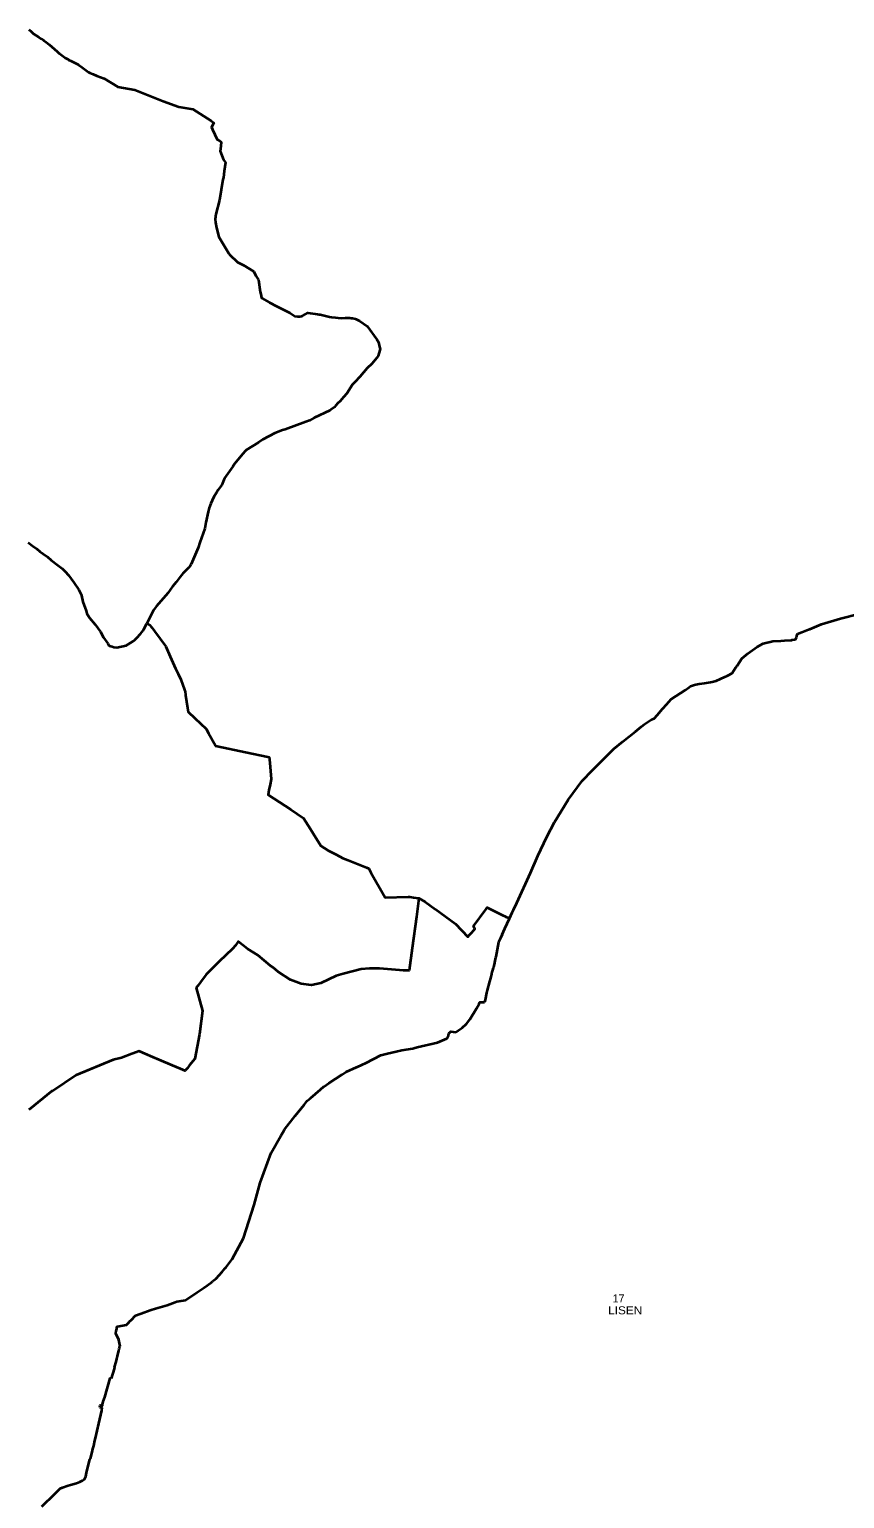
# Model space of a CAD drawing. Extents: x -610940 to -588976, y -1170376 to -1149800.
# Drawn here: x -594068 to -591522, y -1160628 to -1156037 of the extents above; entities that cross this region are included whole.
import ezdxf

# ---------------------------------------------------------------- set-up
doc = ezdxf.new("R2010")
doc.units = 0
doc.header["$LTSCALE"] = 10
doc.layers.add('54', color=7, linetype='Continuous', lineweight=35)
doc.layers.add('55', color=7, linetype='Continuous')
doc.layers.add('56', color=7, linetype='Continuous')

msp = doc.modelspace()

# ---------------------------------------------------------------- linework, layer by layer
at = {"layer": '54'}
for p, q in [((-592620.5, -1158973.98), (-592623.43, -1158983.47)), ((-592619.05, -1158968.17), (-592620.5, -1158973.98)), ((-592659.46, -1159076.98), (-592658.44, -1159076.99)), ((-592655.5, -1159077.04), (-592647.48, -1159077.18)), ((-592744.47, -1159169.7), (-592736.44, -1159170.78)), ((-593237.63, -1159432.35), (-593209.8, -1159397.39)), ((-593701.88, -1160043.06), (-593688.14, -1160038.12)), ((-593841.53, -1160352.31), (-593840.77, -1160344.11)), ((-594000.97, -1160625), (-593995.65, -1160620))]:
    msp.add_line(p, q, dxfattribs=at)
for points in [[(-594069.79, -1156037.15), (-594062.47, -1156043.95), (-594055.33, -1156050.58), (-594054.77, -1156050.95), (-594046.76, -1156056.24), (-594039.02, -1156061.36), (-594031.05, -1156066.63), (-594023.9, -1156071.35), (-594023.26, -1156071.81), (-594015.19, -1156077.58), (-594006.33, -1156083.91), (-594005.96, -1156084.24), (-593998.04, -1156091.35), (-593990, -1156098.56), (-593981.65, -1156106.05), (-593976.34, -1156111.24), (-593973.67, -1156112.71), (-593965.38, -1156119), (-593961.28, -1156122.1), (-593955.87, -1156125.6), (-593946.37, -1156131.73), (-593946.13, -1156131.84), (-593936.72, -1156136.45), (-593925.95, -1156141.72), (-593916.16, -1156146.52), (-593915.09, -1156147.46), (-593914.77, -1156147.68), (-593904.17, -1156155.24), (-593891.43, -1156164.31), (-593883.88, -1156170.56), (-593879.19, -1156172.57), (-593869.12, -1156177.32), (-593857.62, -1156182.75)], [(-593857.62, -1156182.75), (-593834.8, -1156190.12), (-593791.84, -1156217), (-593738.88, -1156226.42), (-593733.86, -1156228.63), (-593702.14, -1156241.11), (-593649.76, -1156261.34), (-593601.64, -1156279.3), (-593557.9, -1156286.82), (-593499.91, -1156322.68), (-593491.52, -1156329.58), (-593499.53, -1156342.24), (-593495.97, -1156350.49), (-593481.7, -1156380.78), (-593476.08, -1156383.18), (-593468.86, -1156389.28), (-593470.91, -1156410.93), (-593472.55, -1156417.18), (-593462.02, -1156445.06), (-593455.69, -1156452.71), (-593459.58, -1156480.35), (-593462.01, -1156500.12), (-593463.43, -1156506.51), (-593474.75, -1156571.22), (-593485.63, -1156614.98), (-593487.32, -1156630.19), (-593486.55, -1156640.25), (-593483.25, -1156657.26), (-593475.86, -1156685.73), (-593445.64, -1156737.9), (-593443.48, -1156740.73), (-593417.94, -1156765.02), (-593399.28, -1156773.41), (-593366.69, -1156793.65), (-593360.55, -1156806.97), (-593352.81, -1156820.08), (-593346.99, -1156856.74), (-593345.5, -1156864.12), (-593343.51, -1156875.89), (-593342.45, -1156876.95)], [(-593342.45, -1156876.95), (-593318.56, -1156890.33), (-593296.11, -1156902.49), (-593255.02, -1156922.92), (-593238.86, -1156932.97), (-593230.3, -1156934.39), (-593226.2, -1156934.61), (-593222.89, -1156934.51), (-593218.56, -1156933.69), (-593214.88, -1156932.45), (-593205.61, -1156927.12), (-593198.08, -1156923), (-593167.89, -1156927.3), (-593163.45, -1156927.68), (-593159.39, -1156928.25), (-593130.71, -1156935.56), (-593124.59, -1156936.71), (-593112.37, -1156937.72), (-593104.12, -1156938.75), (-593092.74, -1156939.19), (-593081.51, -1156938.49), (-593070.1, -1156938.27), (-593066.78, -1156938.36), (-593063.13, -1156939.04), (-593059.37, -1156940), (-593049.81, -1156942.01), (-593048.18, -1156942.57), (-593047.13, -1156942.92), (-593036.74, -1156948.05), (-593013.44, -1156964.31), (-592983.04, -1157006.13), (-592977.4, -1157014.4), (-592974.55, -1157029.02), (-592972.78, -1157035.67), (-592973.65, -1157039.42), (-592978.42, -1157057.33), (-592983.09, -1157063), (-592998.57, -1157082.68), (-593013.1, -1157095.82), (-593035.93, -1157122.97)], [(-593035.93, -1157122.97), (-593052, -1157139.17), (-593058.82, -1157146.28), (-593076.67, -1157174.69), (-593086.92, -1157186.59), (-593097.44, -1157199.16), (-593104.17, -1157205.57), (-593112.11, -1157213.61), (-593115.5, -1157217.85), (-593125.7, -1157225.03), (-593129.55, -1157227.92), (-593178.36, -1157251.26), (-593193.66, -1157258.82), (-593204.39, -1157263.8), (-593268.82, -1157287.15), (-593277.57, -1157289.02), (-593301.05, -1157298.73), (-593338.79, -1157318.69), (-593352.55, -1157327.64), (-593390.06, -1157350.68), (-593394.27, -1157355.03), (-593401.38, -1157363.13), (-593427.12, -1157394.33), (-593433.05, -1157402.77), (-593458.23, -1157439.86), (-593463.08, -1157450.12), (-593467.16, -1157459.95), (-593478.58, -1157476.08), (-593483.1, -1157483.24), (-593491.64, -1157498.04), (-593497.4, -1157508.92), (-593501.35, -1157518.21), (-593506.52, -1157532.12), (-593510.06, -1157544.44), (-593516.89, -1157578.14), (-593520.5, -1157596.82), (-593535.54, -1157640.12), (-593540.82, -1157656.62), (-593550.38, -1157679.12), (-593562.92, -1157707.85)], [(-594072.16, -1157640.36), (-594058.55, -1157650.67), (-594045.24, -1157660.51), (-594035.66, -1157668.28), (-594024.77, -1157675.54), (-594011.9, -1157685.55), (-594000.02, -1157695.45), (-593978.19, -1157712.07), (-593966.14, -1157721.54), (-593956.07, -1157730.91), (-593945.72, -1157742.84), (-593929.39, -1157765.22), (-593929.13, -1157765.62), (-593913.95, -1157788.72), (-593907.32, -1157801.34), (-593905.73, -1157805.8), (-593900.74, -1157825.38), (-593891.09, -1157853.98)], [(-593562.92, -1157707.85), (-593566.26, -1157713.46), (-593570.58, -1157718.98), (-593577.13, -1157725.77), (-593588.64, -1157737.11), (-593597.16, -1157747.75), (-593609.73, -1157763.95), (-593620.6, -1157777.65), (-593635.75, -1157798.36), (-593671.14, -1157839.67), (-593680.79, -1157852.12), (-593701.01, -1157893.15)], [(-593891.09, -1157853.98), (-593888.32, -1157862.18), (-593880.11, -1157875.63), (-593862.71, -1157896.26), (-593845.59, -1157919.5), (-593836.19, -1157937.04), (-593823.05, -1157956.32), (-593819.62, -1157962.1), (-593818.37, -1157962.89), (-593809.36, -1157965.88), (-593804.56, -1157967.18), (-593795.33, -1157968.43), (-593765.63, -1157961.83), (-593760.93, -1157959.27), (-593744.41, -1157949.12), (-593740.22, -1157946.06), (-593737.6, -1157943.27), (-593732.15, -1157937.94), (-593720.85, -1157925.34), (-593712.5, -1157915.49), (-593710.45, -1157911.1), (-593701.01, -1157893.15), (-593692.37, -1157898.58), (-593688.12, -1157903.54), (-593685.85, -1157906.48), (-593677.56, -1157917.18), (-593641.93, -1157965.55), (-593628.14, -1157997.11), (-593620.22, -1158015.22), (-593611.33, -1158033.93), (-593603.82, -1158050.67), (-593595.12, -1158068.75), (-593583.43, -1158100.91), (-593582.41, -1158103.73), (-593581.75, -1158104.67), (-593580.19, -1158117.8), (-593574.21, -1158156.71), (-593572.44, -1158169.19), (-593551.34, -1158189.22), (-593516.26, -1158222.24)], [(-591890.72, -1158057.76), (-591879.98, -1158052.5), (-591879.66, -1158052.34), (-591872.6, -1158048.28), (-591862.33, -1158032.56), (-591857.89, -1158025.76), (-591843.18, -1158003.24), (-591823.72, -1157987.1), (-591795.28, -1157966.4), (-591783.13, -1157959.89), (-591777.95, -1157957.12), (-591776.58, -1157956.38), (-591745.74, -1157949.16), (-591720.56, -1157947.51), (-591709.35, -1157946.77), (-591687.28, -1157945.32), (-591685.9, -1157944.99), (-591678.59, -1157943.27), (-591673.82, -1157942.14), (-591673.01, -1157939.15), (-591672.5, -1157937.28), (-591671.1, -1157932.71), (-591669.67, -1157928.06), (-591668.99, -1157925.84), (-591655.97, -1157920.77), (-591655.15, -1157920.45), (-591634.88, -1157912.48), (-591634.18, -1157912.21), (-591630.64, -1157910.76), (-591594.28, -1157895.84), (-591535.12, -1157877.64), (-591477.78, -1157863.42)], [(-592568.2, -1158815.5), (-592559.89, -1158796.3), (-592559.08, -1158794.59), (-592556.8, -1158789.82), (-592556.2, -1158788.55), (-592545.43, -1158766.52), (-592502.98, -1158672.86), (-592480.16, -1158619.88), (-592451.88, -1158560.54), (-592427.6, -1158514.54), (-592407.8, -1158481.6), (-592385.08, -1158444.08), (-592341.11, -1158385.45), (-592309.32, -1158352.26), (-592242.3, -1158284.85), (-592214.63, -1158262.47), (-592174.72, -1158231.04), (-592156.45, -1158215.65), (-592147.2, -1158207.86), (-592125.26, -1158193.82), (-592117.02, -1158190.52), (-592106.34, -1158178.43), (-592091.54, -1158161.68), (-592089.53, -1158159.43), (-592078.29, -1158146.83), (-592063.58, -1158130.34), (-592020.07, -1158101.56), (-592008.29, -1158093.8), (-592003.3, -1158089.56), (-591997.05, -1158087.2), (-591990.44, -1158084.7), (-591986.47, -1158084.02), (-591976.64, -1158082.34), (-591959.88, -1158079.65), (-591953.22, -1158078.58), (-591941.17, -1158076.6), (-591935.94, -1158075.74), (-591923.28, -1158072.22), (-591896.28, -1158060.48), (-591890.72, -1158057.76)], [(-593516.26, -1158222.24), (-593508.56, -1158236.26), (-593486.64, -1158275.19), (-593486.5, -1158275.43), (-593481.7, -1158276.44), (-593392.69, -1158295.09), (-593323.62, -1158310.31), (-593318.9, -1158311.17), (-593318.69, -1158313.96), (-593318.49, -1158316.42), (-593318.26, -1158319.33), (-593317.48, -1158329.35), (-593313.09, -1158380.08), (-593316.15, -1158396.24), (-593319.89, -1158414.26), (-593322.78, -1158428.46), (-593251.86, -1158475.13), (-593211.98, -1158501.42), (-593190.36, -1158536.12), (-593181.92, -1158550), (-593158.02, -1158588.68), (-593134.9, -1158602.57), (-593109.92, -1158615.68), (-593088.67, -1158626.83), (-593072.17, -1158633.35), (-593014.68, -1158656.36), (-593008.06, -1158659.01), (-593001.2, -1158671.74), (-592956.83, -1158749.95), (-592884.76, -1158747.84), (-592880.22, -1158747.4), (-592868.83, -1158749.32), (-592851.88, -1158751.67), (-592859.44, -1158810.24), (-592872.02, -1158907.98), (-592881.57, -1158977.77), (-592899.72, -1158977.73), (-592949.47, -1158973.17), (-592974.31, -1158971.71), (-593005.79, -1158971.46)], [(-592851.88, -1158751.67), (-592831.73, -1158763.63), (-592800.29, -1158785.87), (-592799.26, -1158786.32), (-592768.49, -1158809.34), (-592737.54, -1158832.41), (-592698.8, -1158872.63), (-592693.58, -1158865.85), (-592689.67, -1158862.54), (-592678.21, -1158849.49), (-592676.34, -1158847.08), (-592681.15, -1158838.88), (-592642.95, -1158787.21), (-592638.22, -1158780.91), (-592594.58, -1158802.46), (-592590.34, -1158804.56), (-592581.48, -1158809.07), (-592580.06, -1158809.64), (-592573.96, -1158812.65), (-592568.2, -1158815.5)], [(-592591.68, -1158865.34), (-592583.52, -1158846.28), (-592568.2, -1158815.5)], [(-593005.79, -1158971.46), (-593032.33, -1158973.21), (-593088.18, -1158988.43), (-593109.4, -1158994.52), (-593158.03, -1159017.72), (-593187.38, -1159023.39), (-593219.34, -1159019.84), (-593252.11, -1159006.94), (-593290.84, -1158981.83), (-593307.06, -1158968.4), (-593314.63, -1158962.67), (-593354.41, -1158929.76), (-593387.04, -1158910.38), (-593415.65, -1158886.99), (-593420.43, -1158893.33), (-593424.83, -1158899.17), (-593433.31, -1158910.42), (-593474.86, -1158949.37), (-593516.41, -1158990.47), (-593533.65, -1159013.99), (-593542.45, -1159025.29), (-593547.37, -1159032.01), (-593527.28, -1159104.13), (-593536.78, -1159176.63), (-593551.59, -1159253.65), (-593567.52, -1159273.66), (-593574.68, -1159282.82), (-593579.97, -1159289.6), (-593581.06, -1159290.99), (-593596.29, -1159284.65), (-593621.46, -1159274.17), (-593662.63, -1159257.03), (-593682.61, -1159248.24), (-593706.44, -1159237.76), (-593713.37, -1159234.72), (-593724.72, -1159229.73), (-593728.18, -1159231.03), (-593729.5, -1159231.33), (-593732, -1159232.47), (-593733.39, -1159232.81)], [(-592591.68, -1158865.34), (-592596.6, -1158876.31), (-592602.45, -1158889.75), (-592611.61, -1158935.19), (-592611.96, -1158936.93), (-592615.41, -1158953), (-592615.78, -1158954.71), (-592617.55, -1158961.81), (-592617.93, -1158963.36), (-592618.82, -1158967.28), (-592619.05, -1158968.17)], [(-592623.43, -1158983.47), (-592624.61, -1158987.52), (-592624.81, -1158989.28)], [(-592624.81, -1158989.28), (-592628, -1159002.07), (-592630.51, -1159012.16), (-592638.32, -1159039.37), (-592640.32, -1159047.12), (-592644.8, -1159069.27), (-592646.45, -1159077.2)], [(-592736.44, -1159170.78), (-592735.64, -1159170.18), (-592728.77, -1159165.05), (-592716.5, -1159157.13), (-592703.14, -1159144.21), (-592692.2, -1159130.8), (-592672, -1159096.62), (-592663.37, -1159082.02), (-592660.83, -1159076.95), (-592659.46, -1159076.98)], [(-592658.44, -1159076.99), (-592656.36, -1159077.03), (-592655.5, -1159077.04)], [(-592647.48, -1159077.18), (-592646.99, -1159077.19), (-592646.45, -1159077.2)], [(-593209.8, -1159397.39), (-593200.34, -1159385.51), (-593189.79, -1159376.41), (-593158.73, -1159349.61), (-593147.9, -1159340.26), (-593147.33, -1159339.77), (-593132.49, -1159329.91), (-593091.18, -1159302.46), (-593078.71, -1159294.17), (-593046.84, -1159279.9), (-593043.39, -1159278.36), (-593016.27, -1159266.22), (-592970.85, -1159242.06), (-592949.61, -1159237.16), (-592922.44, -1159230.9), (-592904.88, -1159226.85), (-592870.35, -1159220.99), (-592867.42, -1159220.28), (-592856.92, -1159217.75), (-592793.25, -1159202.39), (-592764.02, -1159189.98), (-592759.15, -1159180.99), (-592757.96, -1159173.81), (-592755.85, -1159172.68), (-592751.44, -1159168.77), (-592744.47, -1159169.7)], [(-593733.39, -1159232.81), (-593747.96, -1159238.34), (-593779.9, -1159250.53), (-593806.69, -1159256.94), (-593922.32, -1159304.87), (-593995.51, -1159355.21), (-593997.18, -1159354.17), (-594069.29, -1159413.18)], [(-593688.14, -1160038.12), (-593674.08, -1160034.01), (-593637.31, -1160023.26), (-593613.2, -1160014.56), (-593607.4, -1160012.46), (-593607.03, -1160012.33), (-593600.36, -1160011.22), (-593580.55, -1160007.94), (-593544.87, -1159983.88), (-593523.17, -1159969.25), (-593513.19, -1159961.79), (-593497.46, -1159950.04), (-593496.04, -1159948.88), (-593493.52, -1159946.82), (-593485.14, -1159939.97), (-593465.52, -1159919.17), (-593457.5, -1159908.78), (-593453.76, -1159904.73), (-593435.18, -1159880.11), (-593399.22, -1159813.8), (-593366.26, -1159710.42), (-593347.5, -1159641.69), (-593312.93, -1159547.7), (-593282.39, -1159494.07), (-593273.64, -1159478.7), (-593271.38, -1159474.74), (-593237.63, -1159432.35)], [(-593801.75, -1160217.17), (-593797.42, -1160200.8), (-593795.03, -1160191.4), (-593792.9, -1160182.6), (-593791.62, -1160178), (-593788.73, -1160166.58), (-593787.3, -1160159.91), (-593785.44, -1160153.02), (-593784.92, -1160151.13), (-593784.64, -1160150.12), (-593785.23, -1160147.5), (-593788.67, -1160132.22), (-593798.24, -1160111.88), (-593796.51, -1160103.26), (-593796.16, -1160101.48), (-593793.82, -1160089.83), (-593765.26, -1160084.62), (-593757.88, -1160077.44), (-593755.98, -1160075.55), (-593747.92, -1160067.74), (-593747.11, -1160066.86), (-593739.39, -1160058.47), (-593736.75, -1160055.6), (-593707.26, -1160045), (-593701.88, -1160043.06)], [(-593801.75, -1160217.17), (-593803.43, -1160222.72), (-593812.49, -1160252.61)], [(-593848.54, -1160342.1), (-593848.44, -1160341.66), (-593847.22, -1160336.17), (-593847.12, -1160335.73), (-593840.18, -1160337.24), (-593839.86, -1160333.51), (-593837.66, -1160324.08), (-593832.23, -1160311.35), (-593816.2, -1160251.6), (-593812.49, -1160252.61)], [(-593964.5, -1160593.55), (-593947.16, -1160587.27), (-593939.23, -1160584.4), (-593921.1, -1160579.57), (-593910.5, -1160575.88), (-593902.34, -1160571.56), (-593896.34, -1160567.29), (-593892.71, -1160560.59), (-593891.83, -1160558.35), (-593889.32, -1160547.49), (-593886.45, -1160534.27), (-593885.55, -1160530.88), (-593880.1, -1160508.76), (-593879.04, -1160506.2), (-593876.8, -1160502.49), (-593875.65, -1160499.12), (-593870.8, -1160478), (-593869.39, -1160472.1), (-593867.22, -1160462.91), (-593863.43, -1160446.1), (-593861.7, -1160439.23), (-593850.93, -1160392.78), (-593841.53, -1160352.31)], [(-593848.54, -1160342.1), (-593842.71, -1160343.61), (-593840.77, -1160344.11)], [(-594000.97, -1160625), (-594018.8, -1160642.48), (-594025.31, -1160648.86), (-594029.97, -1160653.43)], [(-593995.65, -1160620), (-593984.67, -1160608.93), (-593972.45, -1160596.59), (-593964.5, -1160593.55)]]:
    msp.add_lwpolyline(points, dxfattribs=at)

# ---------------------------------------------------------------- texts
at = {"layer": '55', "width": 1.1}
msp.add_text('LISEN ', height=25, dxfattribs=at).set_placement((-592260.33, -1160052.02))
at = {"layer": '56'}
msp.add_text('17 ', height=25, dxfattribs=at).set_placement((-592246.52, -1160014.84))

doc.saveas('drawing.dxf')
